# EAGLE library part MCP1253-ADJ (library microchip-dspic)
Positive-Regulated Adjustable Charge Pump
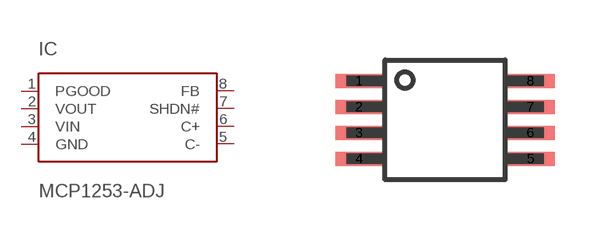
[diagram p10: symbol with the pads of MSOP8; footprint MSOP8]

Designator prefix IC

## MCP1253-ADJ  [MSOP8]
1  PGOOD  oc
2  VOUT  sup
3  VIN  pwr
4  GND  pwr
5  C-  pas
6  C+  pas
7  SHDN#  in
8  FB  in

## Footprint MSOP8 (pad centres in mm)
Micro Small Outline Package
smd 1.2 x 0.35: 1 -2.145,0.975; 2 -2.145,0.325; 3 -2.145,-0.325; 4 -2.145,-0.975; 5 2.145,-0.975; 6 2.145,-0.325; 7 2.145,0.325; 8 2.145,0.975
